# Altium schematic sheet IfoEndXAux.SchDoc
size C; Engineer: Daniel Sigg; DocumentNumber: 8; SheetNumber: 27; SheetTotal: 33
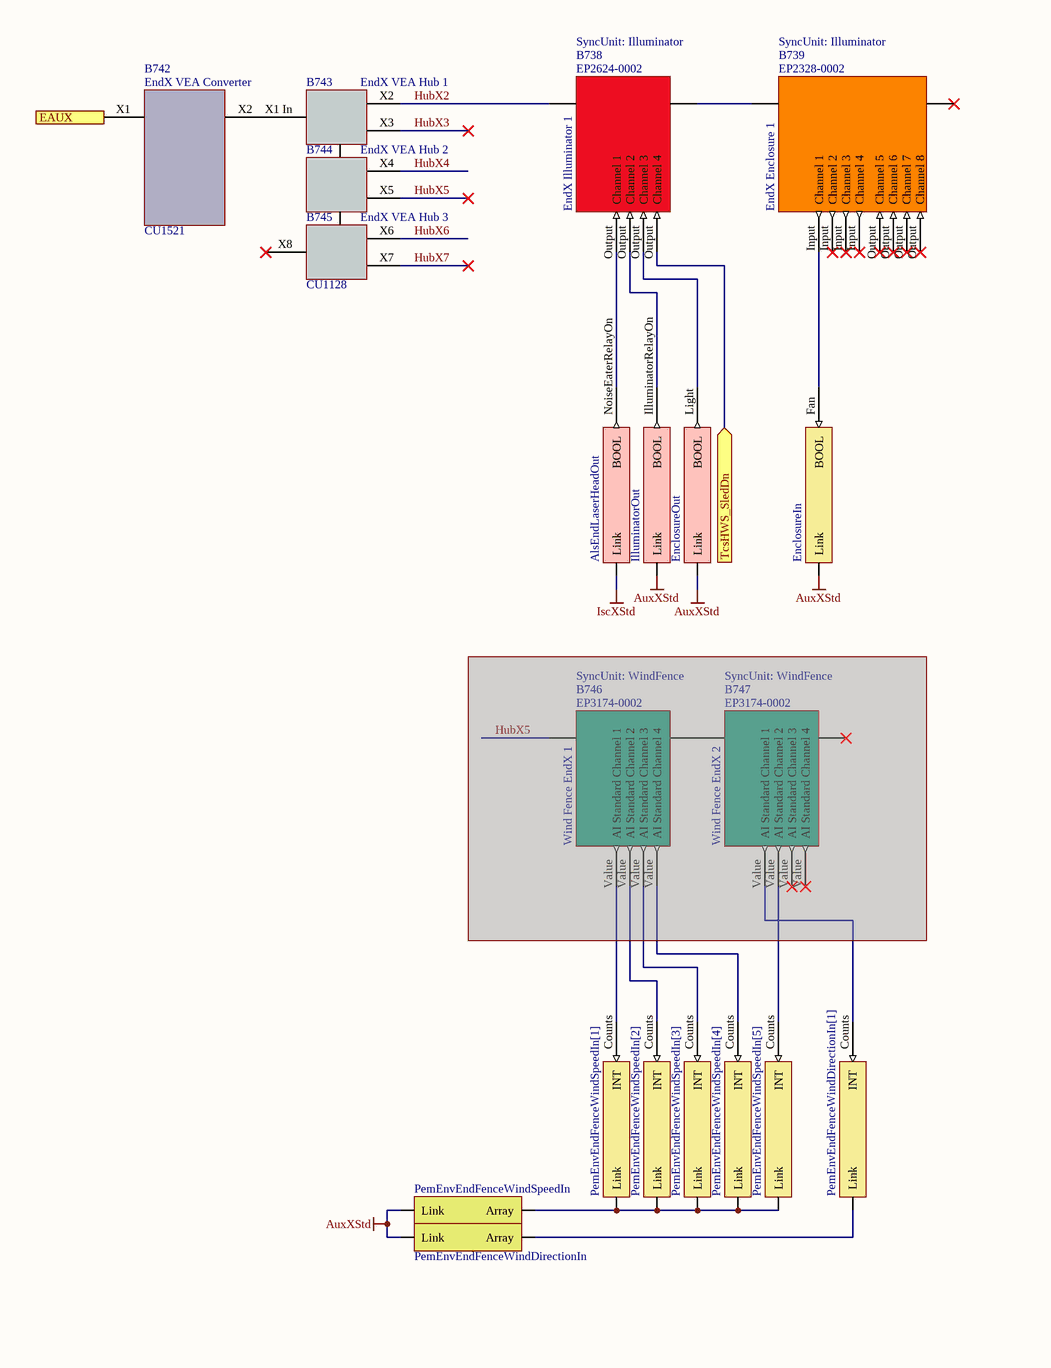
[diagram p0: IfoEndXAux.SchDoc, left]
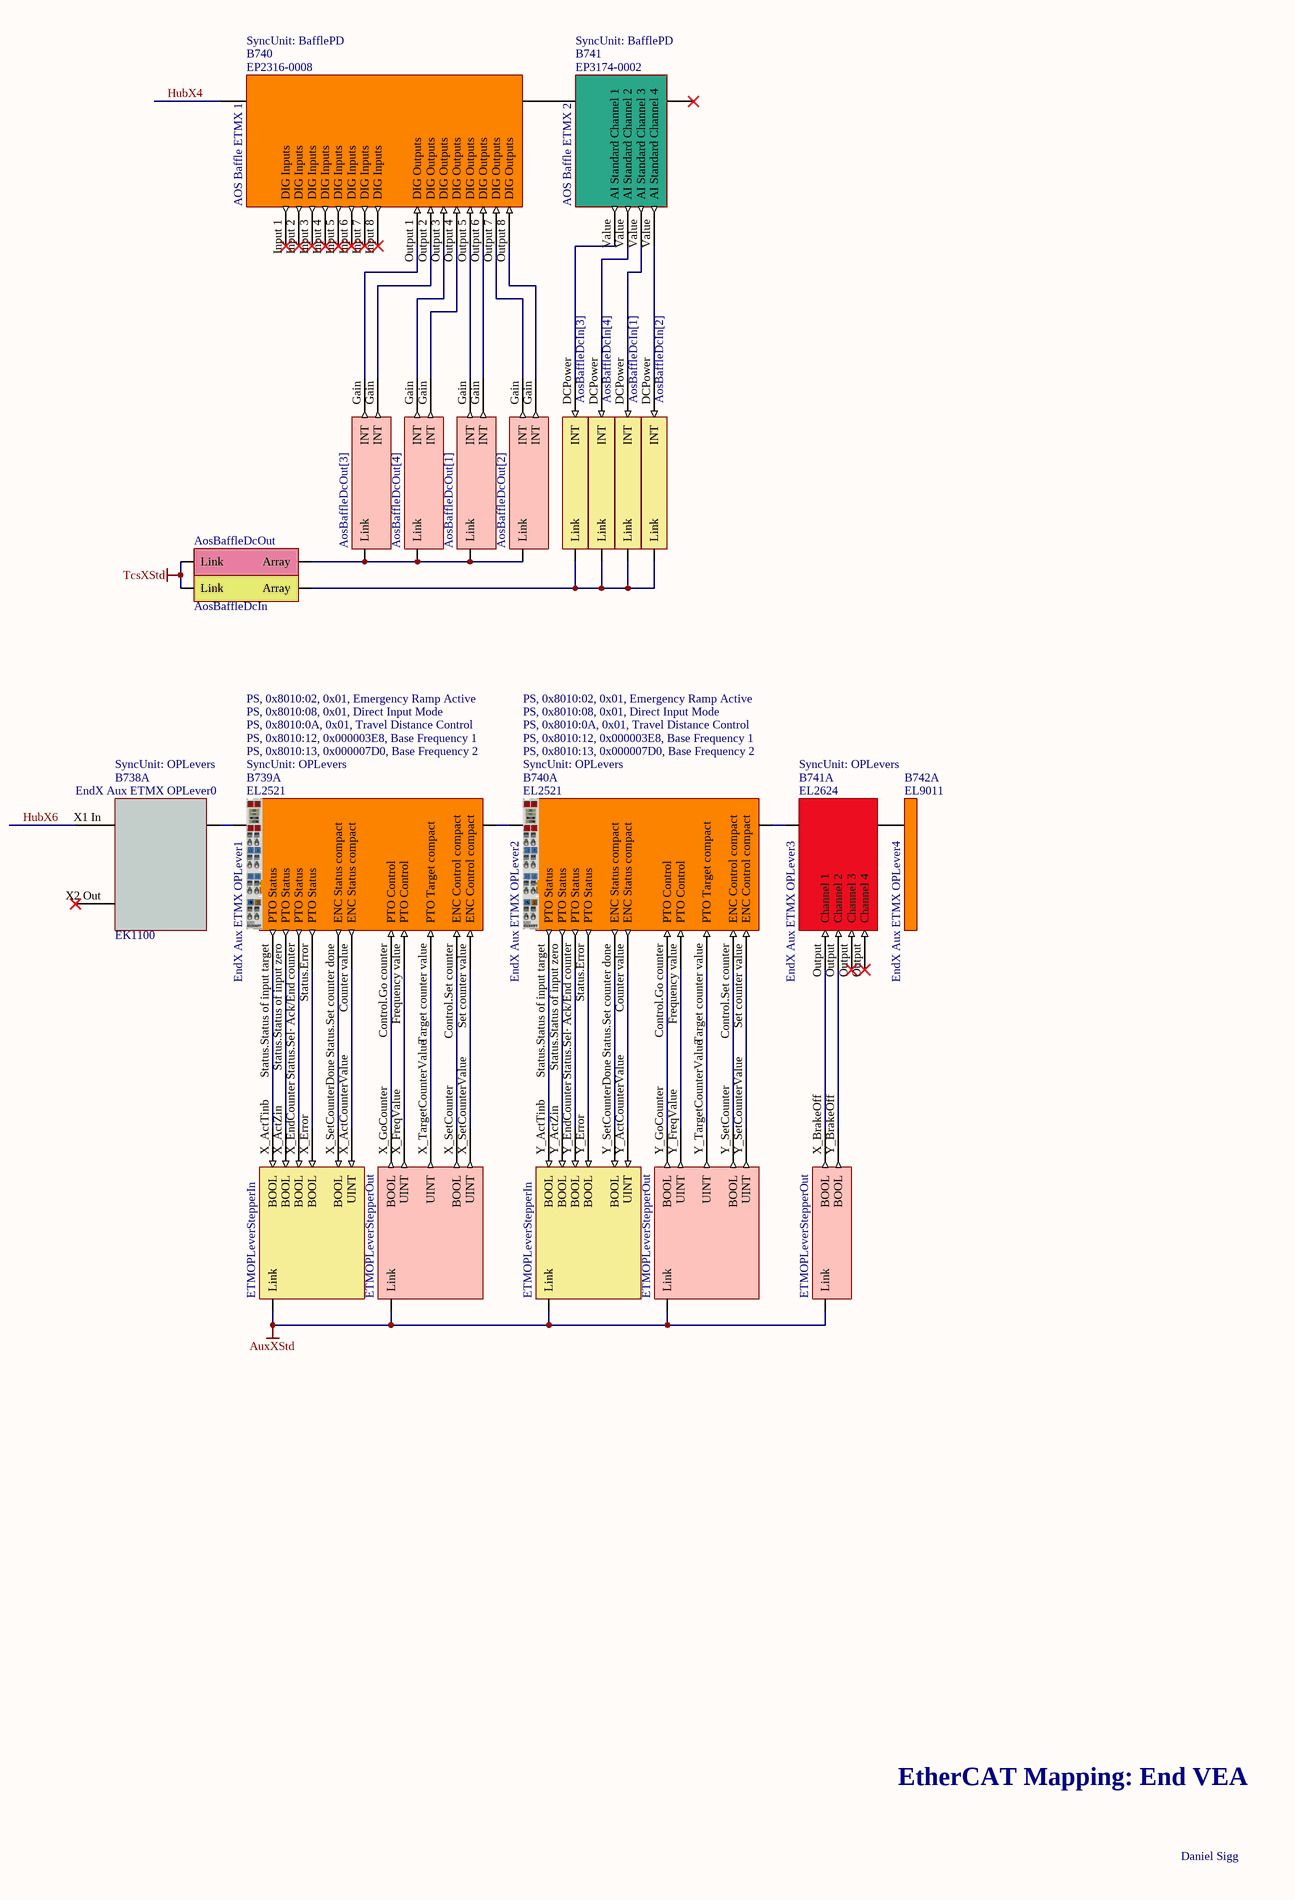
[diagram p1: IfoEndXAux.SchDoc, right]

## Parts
B738  EndX Illuminator 1  Part Number: EP2624-0002  SyncUnit: Illuminator  (mechanical)
B738A  EndX Aux ETMX OPLever0  SyncUnit: OPLevers  Part Number: EK1100  (mechanical)
B739  EndX Enclosure 1  SyncUnit: Illuminator  Part Number: EP2328-0002  (mechanical)
B739A  EndX Aux ETMX OPLever1  SyncUnit: OPLevers  Part Number: EL2521  Init0Cmd: PS, 0x8010:02, 0x01, Emergency Ramp Active  Init1Cmd: PS, 0x8010:08, 0x01, Direct Input Mode  Init2Cmd: PS, 0x8010:0A, 0x01, Travel Distance Control  Init3Cmd: PS, 0x8010:12, 0x000003E8, Base Frequency 1  Init4Cmd: PS, 0x8010:13, 0x000007D0, Base Frequency 2  (mechanical)
B740  AOS Baffle ETMX 1  Part Number: EP2316-0008  SyncUnit: BafflePD  (mechanical)
B740A  EndX Aux ETMX OPLever2  SyncUnit: OPLevers  Part Number: EL2521  Init0Cmd: PS, 0x8010:02, 0x01, Emergency Ramp Active  Init1Cmd: PS, 0x8010:08, 0x01, Direct Input Mode  Init2Cmd: PS, 0x8010:0A, 0x01, Travel Distance Control  Init3Cmd: PS, 0x8010:12, 0x000003E8, Base Frequency 1  Init4Cmd: PS, 0x8010:13, 0x000007D0, Base Frequency 2  (mechanical)
B741  AOS Baffle ETMX 2  Part Number: EP3174-0002  SyncUnit: BafflePD  (mechanical)
B741A  EndX Aux ETMX OPLever3  SyncUnit: OPLevers  Part Number: EL2624  (mechanical)
B742  EndX VEA Converter  Part Number: CU1521  (mechanical)
B742A  EndX Aux ETMX OPLever4  Part Number: EL9011  (mechanical)
B743  EndX VEA Hub 1  Part Number: CU1128  (mechanical)
B744  EndX VEA Hub 2  (mechanical)
B745  EndX VEA Hub 3  (mechanical)
B746  Wind Fence EndX 1  Part Number: EP3174-0002  SyncUnit: WindFence  (mechanical)  (masked out: inside a compile mask, not in the netlist)
B747  Wind Fence EndX 2  Part Number: EP3174-0002  SyncUnit: WindFence  (mechanical)  (masked out: inside a compile mask, not in the netlist)
V556  AlsEndLaserHeadOut  (part B of 2)  (no BOM)
V597  IlluminatorOut  (no BOM)
V597A  ETMOPLeverStepperIn  (parts A,B of 2)  (no BOM)
V598  EnclosureOut  (no BOM)
V598A  ETMOPLeverStepperOut  (parts A,B,C of 3)  (no BOM)
V599  EnclosureIn  (no BOM)
V600  AosBaffleDcOut[3]  (no BOM)
V601  AosBaffleDcOut[4]  (no BOM)
V602  AosBaffleDcOut[1]  (no BOM)
V603  AosBaffleDcOut[2]  (no BOM)
V604  AosBaffleDcIn[3]  (no BOM)
V605  AosBaffleDcIn[4]  (no BOM)
V606  AosBaffleDcIn[1]  (no BOM)
V607  AosBaffleDcIn[2]  (no BOM)
V608  AosBaffleDcOut  (no BOM)
V609  AosBaffleDcIn  (no BOM)
V610  PemEnvEndFenceWindSpeedIn[1]  (no BOM)
V611  PemEnvEndFenceWindSpeedIn[2]  (no BOM)
V612  PemEnvEndFenceWindSpeedIn[3]  (no BOM)
V613  PemEnvEndFenceWindSpeedIn[4]  (no BOM)
V614  PemEnvEndFenceWindSpeedIn[5]  (no BOM)
V615  PemEnvEndFenceWindDirectionIn[1]  (no BOM)
V616  PemEnvEndFenceWindSpeedIn  (no BOM)
V617  PemEnvEndFenceWindDirectionIn  (no BOM)

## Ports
EAUX, TcsHWS_SledDn (in)

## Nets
AuxXStd: V597.0(Link) V597A.0(Link) V597A.1(Link) V598.?1(Link) V598A.0(Link) V598A.1(Link) V598A.2(Link) V599.1(Link) V616.?1(Link) V617.?1(Link)
IscXStd: V556.1(Link)
TcsXStd: V608.?1(Link) V609.?1(Link)
EAUX: B742.X1(A) ; port EAUX
HubX2: B738.?2(A) B743.X2(D)
HubX3: B743.X3(B)
HubX4: B740.?2(A) B744.X4(D)
HubX5: B744.X5(B)
HubX6: B738A.X1_In(A) B745.X6(D)
HubX7: B745.X7(B)
TcsHWS_SledDn: B738.Output(Channel_4) ; port TcsHWS_SledDn
NetB738_?1: B738.?1(B) B739.?2(A)
NetB738_Output: B738.Output(Channel_1) V556.NoiseEaterRelayOn(BOOL)
NetB738_Output: B738.Output(Channel_2) V597.IlluminatorRelayOn(BOOL)  [a separate net that carries the same name]
NetB738_Output: B738.Output(Channel_3) V598.Light(BOOL)  [a separate net that carries the same name]
NetB738A_Ebus: B738A.Ebus(B) B739A.Ebus(A)
NetB739_Input: B739.Input(Channel_1) V599.Fan(BOOL)
NetB739A_Control.Go counter: B739A.Control.Go_counter(PTO_Control) V598A.X_GoCounter(BOOL)
NetB739A_Control.Set counter: B739A.Control.Set_counter(ENC_Control_compact) V598A.X_SetCounter(BOOL)
NetB739A_Counter value: B739A.Counter_value(ENC_Status_compact) V597A.X_ActCounterValue(UINT)
NetB739A_Ebus: B739A.Ebus(B) B740A.Ebus(A)
NetB739A_Frequency value: B739A.Frequency_value(PTO_Control) V598A.X_FreqValue(UINT)
NetB739A_Set counter value: B739A.Set_counter_value(ENC_Control_compact) V598A.X_SetCounterValue(UINT)
NetB739A_Status.Error: B739A.Status.Error(PTO_Status) V597A.X_Error(BOOL)
NetB739A_Status.Sel· Ack/End counter: B739A.Status.Sel·_Ack/End_counter(PTO_Status) V597A.X_EndCounter(BOOL)
NetB739A_Status.Set counter done: B739A.Status.Set_counter_done(ENC_Status_compact) V597A.X_SetCounterDone(BOOL)
NetB739A_Status.Status of input target: B739A.Status.Status_of_input_target(PTO_Status) V597A.X_ActTinb(BOOL)
NetB739A_Status.Status of input zero: B739A.Status.Status_of_input_zero(PTO_Status) V597A.X_ActZin(BOOL)
NetB739A_Target counter value: B739A.Target_counter_value(PTO_Target_compact) V598A.X_TargetCounterValue(UINT)
NetB740_?1: B740.?1(B) B741.?2(A)
NetB740_Output 1: B740.Output_1(DIG_Outputs) V600.Gain(INT)
NetB740_Output 2: B740.Output_2(DIG_Outputs) V600.Gain(INT)
NetB740_Output 3: B740.Output_3(DIG_Outputs) V601.Gain(INT)
NetB740_Output 4: B740.Output_4(DIG_Outputs) V601.Gain(INT)
NetB740_Output 5: B740.Output_5(DIG_Outputs) V602.Gain(INT)
NetB740_Output 6: B740.Output_6(DIG_Outputs) V602.Gain(INT)
NetB740_Output 7: B740.Output_7(DIG_Outputs) V603.Gain(INT)
NetB740_Output 8: B740.Output_8(DIG_Outputs) V603.Gain(INT)
NetB740A_Control.Go counter: B740A.Control.Go_counter(PTO_Control) V598A.Y_GoCounter(BOOL)
NetB740A_Control.Set counter: B740A.Control.Set_counter(ENC_Control_compact) V598A.Y_SetCounter(BOOL)
NetB740A_Counter value: B740A.Counter_value(ENC_Status_compact) V597A.Y_ActCounterValue(UINT)
NetB740A_Ebus: B740A.Ebus(B) B741A.Ebus(A)
NetB740A_Frequency value: B740A.Frequency_value(PTO_Control) V598A.Y_FreqValue(UINT)
NetB740A_Set counter value: B740A.Set_counter_value(ENC_Control_compact) V598A.Y_SetCounterValue(UINT)
NetB740A_Status.Error: B740A.Status.Error(PTO_Status) V597A.Y_Error(BOOL)
NetB740A_Status.Sel· Ack/End counter: B740A.Status.Sel·_Ack/End_counter(PTO_Status) V597A.Y_EndCounter(BOOL)
NetB740A_Status.Set counter done: B740A.Status.Set_counter_done(ENC_Status_compact) V597A.Y_SetCounterDone(BOOL)
NetB740A_Status.Status of input target: B740A.Status.Status_of_input_target(PTO_Status) V597A.Y_ActTinb(BOOL)
NetB740A_Status.Status of input zero: B740A.Status.Status_of_input_zero(PTO_Status) V597A.Y_ActZin(BOOL)
NetB740A_Target counter value: B740A.Target_counter_value(PTO_Target_compact) V598A.Y_TargetCounterValue(UINT)
NetB741_Value: B741.Value(AI_Standard_Channel_1) V604.DCPower(INT)
NetB741_Value: B741.Value(AI_Standard_Channel_2) V605.DCPower(INT)  [a separate net that carries the same name]
NetB741_Value: B741.Value(AI_Standard_Channel_3) V606.DCPower(INT)  [a separate net that carries the same name]
NetB741_Value: B741.Value(AI_Standard_Channel_4) V607.DCPower(INT)  [a separate net that carries the same name]
NetB741A_Ebus: B741A.Ebus(B) B742A.Ebus(A)
NetB741A_Output: B741A.Output(Channel_1) V598A.X_BrakeOff(BOOL)
NetB741A_Output: B741A.Output(Channel_2) V598A.Y_BrakeOff(BOOL)  [a separate net that carries the same name]
NetB742_X2: B742.X2(B) B743.X1_In(A)
NetB743_Ebus: B743.Ebus(C) B744.Ebus(A)
NetB744_Ebus: B744.Ebus(C) B745.Ebus(A)
NetV600_0: V600.0(Link) V601.0(Link) V602.0(Link) V603.0(Link) V608.?2(Array)
NetV604_1: V604.1(Link) V605.1(Link) V606.1(Link) V607.1(Link) V609.?2(Array)
NetV610_1: V610.1(Link) V611.1(Link) V612.1(Link) V613.1(Link) V614.1(Link) V616.?2(Array)
NetV615_1: V615.1(Link) V617.?2(Array)

Not connected (* = marked no-connect by the designer): B738A X2 Out(C)*; B739 ?1(B)* Output(Channel_5)*; B740 Input 1(DIG_Inputs)* Input 2(DIG_Inputs)* Input 3(DIG_Inputs)* Input 4(DIG_Inputs)* Input 5(DIG_Inputs)* Input 6(DIG_Inputs)* Input 7(DIG_Inputs)* Input 8(DIG_Inputs)*; B741 ?1(B)*; B745 X8(C)*; V610 Counts(INT); V611 Counts(INT); V612 Counts(INT); V613 Counts(INT); V614 Counts(INT); V615 Counts(INT)

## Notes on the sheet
- EtherCAT Mapping: End VEA
- Daniel Sigg

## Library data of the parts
B738 = BoxEP2624-0002: EtherCAT Box EP2624-0002 4-channel relay output 25 V AC/30 V DC; BoxNextB: CLYTKING; BoxPrev: MHYXYRHK; PortPrevFull: 1115/D; PortPrevShort: D 'X2'; Fullname: TIID^End X (EtherCAT)^EndX Link L0 (EK1501-0010)^EndX Link L6 (EK1521)^EndX VEA Hub 1 (CU1128)^EndX Illuminator 1 (EP2624-0002); BoxAddr: 1116; Disabled: False
B738A = CouplerEK1100: EtherCAT Coupler; BoxNextB: TMZMTCVR; BoxPrev: IYIUPWIY; PortPrevFull: 1121/D; PortPrevShort: D 'X6'; Fullname: TIID^End X (EtherCAT)^EndX Link L0 (EK1501-0010)^EndX Link L6 (EK1521)^EndX VEA Hub 1 (CU1128)^EndX VEA Hub 3 (CU1128-0002)^EndX Aux ETMX OPLever0 (EK1100); BoxPorts: Junction; BoxAddr: 1122; Disabled: False
B739 = BoxEP2328-0002: EtherCAT Box EP2328-0002 4 x digital input and 4 x digital output 24 V DC; BoxPrev: MGPGGXOT; PortPrevFull: 1116/B; PortPrevShort: B; Fullname: TIID^End X (EtherCAT)^EndX Link L0 (EK1501-0010)^EndX Link L6 (EK1521)^EndX VEA Hub 1 (CU1128)^EndX Enclosure 1 (EP2328-0002); BoxAddr: 1117; Disabled: False
B739A = TerminalEL2521: EtherCAT Terminal EL2521 1-channel pulse train output, incr. enc. simulation, RS422, 50 mA; BoxNextB: RVWELLIF; BoxPrev: MMENGWJO; PortPrevFull: 1122/B; PortPrevShort: B; Fullname: TIID^End X (EtherCAT)^EndX Link L0 (EK1501-0010)^EndX Link L6 (EK1521)^EndX VEA Hub 1 (CU1128)^EndX VEA Hub 3 (CU1128-0002)^EndX Aux ETMX OPLever0 (EK1100)^EndX Aux ETMX OPLever1 (EL2521); BoxAddr: 1123; PDO Outputs: 0x1601,0x1604,0x1602; PDO Inputs: 0x1A01,0x1A02; Disabled: False
B740 = BoxEP2316-0008: EtherCAT Box EP2316-0008 8 x digital input + 8 x digital output; BoxNextB: PYNMIUIP; BoxPrev: LIKIPXHV; PortPrevFull: 1118/D; PortPrevShort: D 'X4'; Fullname: TIID^End X (EtherCAT)^EndX Link L0 (EK1501-0010)^EndX Link L6 (EK1521)^EndX VEA Hub 1 (CU1128)^EndX VEA Hub 2 (CU1128-0001)^AOS Baffle ETMX 1 (EP2316-0008); BoxAddr: 1119; Disabled: False
B740A = TerminalEL2521: EtherCAT Terminal EL2521 1-channel pulse train output, incr. enc. simulation, RS422, 50 mA; BoxNextB: LBDYYBCS; BoxPrev: TMZMTCVR; PortPrevFull: 1123/B; PortPrevShort: B; Fullname: TIID^End X (EtherCAT)^EndX Link L0 (EK1501-0010)^EndX Link L6 (EK1521)^EndX VEA Hub 1 (CU1128)^EndX VEA Hub 3 (CU1128-0002)^EndX Aux ETMX OPLever0 (EK1100)^EndX Aux ETMX OPLever2 (EL2521); BoxAddr: 1124; PDO Outputs: 0x1601,0x1604,0x1602; PDO Inputs: 0x1A01,0x1A02; Disabled: False
B741 = BoxEP3174-0002: EtherCAT Box EP3174-0002 4-channel analog input ±10 V or 0/4…20 mA, parameterisable, differential input, 16 bit; BoxPrev: BGXIVJGL; PortPrevFull: 1119/B; PortPrevShort: B; Fullname: TIID^End X (EtherCAT)^EndX Link L0 (EK1501-0010)^EndX Link L6 (EK1521)^EndX VEA Hub 1 (CU1128)^EndX VEA Hub 2 (CU1128-0001)^AOS Baffle ETMX 2 (EP3174-0002); BoxAddr: 1120; Disabled: False
B741A = TerminalEL2624: EtherCAT Terminal EL2624 4-channel relay output terminal 125 V AC/30 V DC; BoxNextB: OHMSGVAU; BoxPrev: RVWELLIF; PortPrevFull: 1124/B; PortPrevShort: B; Fullname: TIID^End X (EtherCAT)^EndX Link L0 (EK1501-0010)^EndX Link L6 (EK1521)^EndX VEA Hub 1 (CU1128)^EndX VEA Hub 3 (CU1128-0002)^EndX Aux ETMX OPLever0 (EK1100)^EndX Aux ETMX OPLever3 (EL2624); BoxAddr: 1125; Disabled: False
B742 = MediaConverterFiberToCAT5: EtherCAT Media Converter; BoxType: Box; BoxNextB: MHYXYRHK; BoxPrev: QEYXEFKI; PortPrevFull: 1007/C; PortPrevShort: C 'X2 Out'; Fullname: TIID^End X (EtherCAT)^EndX Link L0 (EK1501-0010)^EndX Link L6 (EK1521)^EndX VEA Converter (CU1521); BoxAddr: 1114; Disabled: False
B742A = TerminalEL9011: EtherCAT Terminal EL9011 End; BoxType: TerminalPassive; BoxPrev: LBDYYBCS; PortPrevShort: B; Fullname: TIID^End X (EtherCAT)^EndX Link L0 (EK1501-0010)^EndX Link L6 (EK1521)^EndX VEA Hub 1 (CU1128)^EndX VEA Hub 3 (CU1128-0002)^EndX Aux ETMX OPLever0 (EK1100)^EndX Aux ETMX OPLever4 (EL9011); Disabled: False
B743 = HubCU1128: EtherCAT Hub; BoxType: Box; BoxNextC: LIKIPXHV; BoxNextD: MGPGGXOT; BoxPrev: EQPTNBUH; PortPrevFull: 1114/B; PortPrevShort: B 'X2'; Fullname: TIID^End X (EtherCAT)^EndX Link L0 (EK1501-0010)^EndX Link L6 (EK1521)^EndX VEA Hub 1 (CU1128); BoxPorts: Junction; BoxAddr: 1115; Disabled: False
B744 = HubCU1128-B: EtherCAT Hub subpart B; Part Number: CU1128-0001; BoxType: Box; BoxNextC: IYIUPWIY; BoxNextD: BGXIVJGL; BoxPrev: MHYXYRHK; PortPrevFull: 1115/C; PortPrevShort: C; Fullname: TIID^End X (EtherCAT)^EndX Link L0 (EK1501-0010)^EndX Link L6 (EK1521)^EndX VEA Hub 1 (CU1128)^EndX VEA Hub 2 (CU1128-0001); BoxPorts: Junction; BoxAddr: 1118; Disabled: False
B745 = HubCU1128-C: EtherCAT Hub subpart C; Part Number: CU1128-0002; BoxType: Box; BoxNextD: MMENGWJO; BoxPrev: LIKIPXHV; PortPrevFull: 1118/C; Fullname: TIID^End X (EtherCAT)^EndX Link L0 (EK1501-0010)^EndX Link L6 (EK1521)^EndX VEA Hub 1 (CU1128)^EndX VEA Hub 3 (CU1128-0002); BoxPorts: Junction; BoxAddr: 1121; Disabled: False
B746 B747 = BoxEP3174-0002: EtherCAT Box EP3174-0002 4-channel analog input ±10 V or 0/4…20 mA, parameterisable, differential input, 16 bit; Disabled: False
V556 = ALSLaser_ALSLaserOutStruct: ALSLaserOutStruct; BoxType: Variable; Instance: H1IscEndX Instance; PLC: H1IscEndX; Task: IscEStd
V597 = Illuminator_IlluminatorOutStruct: IlluminatorOutStruct; BoxType: Variable; Instance: H1AuxEndX Instance; PLC: H1AuxEndX; Task: AuxEStd
V597A = OPLever_OPLeverStepperInStruct: OPLeverStepperInStruct; BoxType: Variable; Instance: H1AuxEndX Instance; PLC: H1AuxEndX; Task: AuxEStd
V598 = Enclosure_EnclosureOutStruct: EnclosureOutStruct; BoxType: Variable; Instance: H1AuxEndX Instance; PLC: H1AuxEndX; Task: AuxEStd
V598A = OPLever_OPLeverStepperOutStruct: OPLeverStepperOutStruct; BoxType: Variable; Instance: H1AuxEndX Instance; PLC: H1AuxEndX; Task: AuxEStd
V599 = Enclosure_EnclosureInStruct: EnclosureInStruct; BoxType: Variable; Instance: H1AuxEndX Instance; PLC: H1AuxEndX; Task: AuxEStd
V600-V603 = DCPower_DCPowerOutStruct: DCPowerOutStruct; BoxType: Variable; Instance: H1TcsEndX Instance; PLC: H1TcsEndX; Task: TcsEStd
V604-V607 = DCPower_DCPowerInStruct: DCPowerInStruct; BoxType: Variable; Instance: H1TcsEndX Instance; PLC: H1TcsEndX; Task: TcsEStd
V608 = ArrayAggregatorOut: Array [1..4] Of DCPowerOutStruct; Instance: H1TcsEndX Instance; PLC: H1TcsEndX; Task: TcsEStd; Lower Bound: 1; Upper Bound: 4
V609 = ArrayAggregatorIn: Array [1..4] Of DCPowerInStruct; Instance: H1TcsEndX Instance; PLC: H1TcsEndX; Task: TcsEStd; Lower Bound: 1; Upper Bound: 4
V610-V614 = WindSpeed_WindSpeedInStruct: WindSpeedInStruct; BoxType: Variable; Instance: H1AuxEndX Instance; PLC: H1AuxEndX; Task: AuxEStd
V615 = WindDirection_WindDirectionInStruct: WindDirectionInStruct; BoxType: Variable; Instance: H1AuxEndX Instance; PLC: H1AuxEndX; Task: AuxEStd
V616 = ArrayAggregatorIn: Array [1..5] Of WindSpeedInStruct; Instance: H1AuxEndX Instance; PLC: H1AuxEndX; Task: AuxEStd; Lower Bound: 1; Upper Bound: 5
V617 = ArrayAggregatorIn: Array [1..1] Of WindDirectionInStruct; Instance: H1AuxEndX Instance; PLC: H1AuxEndX; Task: AuxEStd; Lower Bound: 1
